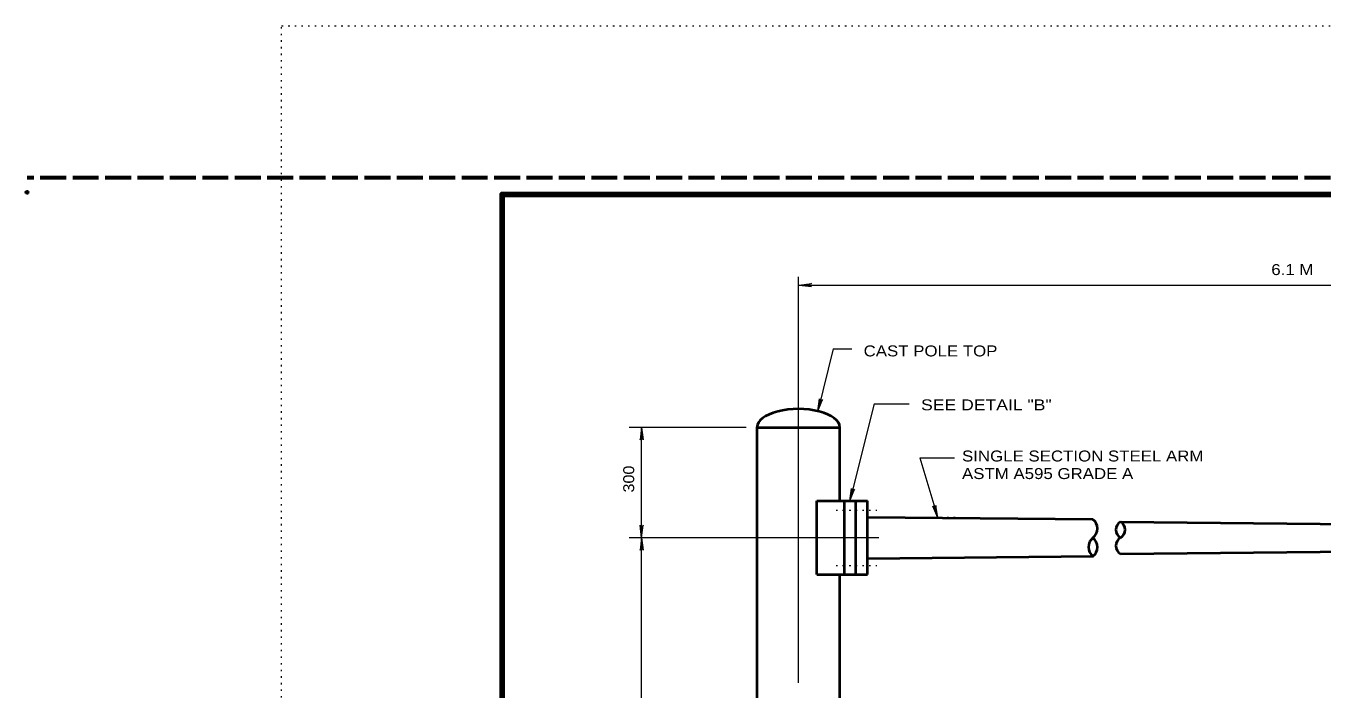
# Model space of a CAD drawing. Extents: x 312583 to 312854, y 144419 to 144597.
# Drawn here: x 312583.5 to 312673.4, y 144550.7 to 144596.8 of the extents above; entities that cross this region are included whole.
import ezdxf

# ---------------------------------------------------------------- set-up
doc = ezdxf.new("R2010")
doc.units = 0
doc.header["$LTSCALE"] = 0.3
doc.header["$PDMODE"] = 32
doc.header["$PDSIZE"] = 0.15
doc.linetypes.add('DOTTED', pattern=[1.5, 0.3, -1.2])
doc.linetypes.add('LONG_DASHED', pattern=[7.5, 6, -1.5])
for name, color, linetype, lineweight in [('1', 7, 'Continuous', 40), ('2', 7, 'Continuous', 13), ('62', 7, 'DOTTED', 13), ('63', 7, 'LONG_DASHED', 60)]:
    doc.layers.add(name, color=color, linetype=linetype, lineweight=lineweight)

msp = doc.modelspace()

# ---------------------------------------------------------------- linework, layer by layer
at = {"layer": '1'}
for p, q in [((312634.1997, 144568.9109), (312639.9497, 144568.9109)), ((312634.1997, 144531.5513), (312634.1997, 144568.9109)), ((312639.9497, 144563.7973), (312639.9497, 144568.9109)), ((312638.3473, 144563.7973), (312641.8663, 144563.7973)), ((312638.3473, 144558.6836), (312638.3473, 144563.7973)), ((312640.264, 144558.6836), (312640.264, 144563.7973)), ((312641.069, 144558.6836), (312641.069, 144563.7973)), ((312641.8663, 144558.6836), (312641.8663, 144563.7973)), ((312641.8663, 144562.6779), (312657.514, 144562.5246)), ((312659.4307, 144562.3559), (312685.9497, 144562.0876)), ((312641.8663, 144559.8029), (312657.5447, 144559.9639)), ((312659.4307, 144560.1249), (312685.9497, 144560.3933)), ((312638.3473, 144558.6836), (312641.8663, 144558.6836)), ((312639.9497, 144531.5513), (312639.9497, 144558.6836))]:
    msp.add_line(p, q, dxfattribs=at)
at = {"layer": '1', "linetype": 'DOTTED', "lineweight": 13}
for p, q in [((312639.6813, 144563.1609), (312642.518, 144563.1609)), ((312641.8663, 144562.6779), (312648.0533, 144562.6779)), ((312639.6813, 144559.3276), (312642.518, 144559.3276))]:
    msp.add_line(p, q, dxfattribs=at)
at = {"layer": '1', "lineweight": 158}
msp.add_lwpolyline([(312616.5, 144423.1446), (312616.5, 144585.0846), (312849, 144585.0846)], dxfattribs=at)
at = {"layer": '1'}
for centre, radius, start, end in [((312657.0179, 144561.8816), 0.8117, 307.90303, 52.09697), ((312659.7626, 144561.8001), 0.6489, 120.51024, 239.48976), ((312659.1038, 144561.8001), 0.6489, 300.51024, 59.48976), ((312658.0152, 144560.6006), 0.8117, 127.90303, 232.09697), ((312657.0179, 144560.6006), 0.8117, 307.90303, 52.09697), ((312659.7626, 144560.682), 0.6489, 120.51024, 239.48976)]:
    msp.add_arc(centre, radius, start, end, dxfattribs=at)
msp.add_ellipse((312637.0721, 144568.9077), major_axis=(2.875, 0), ratio=0.444444, start_param=6.2831853, end_param=9.424778, dxfattribs=at)
msp.add_point((312583.526, 144585.2246), dxfattribs=at)
at = {"layer": '2'}
for p, q in [((312637.0747, 144551.1703), (312637.0747, 144579.3683)), ((312637.1207, 144578.7933), (312637.987, 144578.9006)), ((312637.987, 144578.9006), (312637.711, 144578.7933)), ((312637.1207, 144578.7933), (312706.0747, 144578.7933)), ((312637.1207, 144578.7933), (312637.987, 144578.6859)), ((312637.987, 144578.6859), (312637.711, 144578.7933)), ((312639.4897, 144574.3619), (312638.4317, 144570.0303)), ((312639.4897, 144574.3619), (312640.77, 144574.3619)), ((312638.4317, 144570.0303), (312638.5313, 144570.8966)), ((312638.4317, 144570.0303), (312638.746, 144570.8506)), ((312638.5313, 144570.8966), (312638.5773, 144570.6053)), ((312638.746, 144570.8506), (312638.5773, 144570.6053)), ((312642.3417, 144570.5363), (312640.6473, 144563.7973)), ((312642.3417, 144570.5363), (312644.7643, 144570.5363)), ((312633.456, 144568.9109), (312625.3217, 144568.9109)), ((312626.188, 144568.9109), (312626.0807, 144568.0446)), ((312626.188, 144561.2443), (312626.188, 144568.9109)), ((312626.188, 144568.9109), (312626.2953, 144568.0446)), ((312626.0807, 144568.0446), (312626.188, 144568.3206)), ((312626.2953, 144568.0446), (312626.188, 144568.3206)), ((312645.4927, 144566.7873), (312647.9153, 144566.7873)), ((312645.4927, 144566.7873), (312646.7577, 144562.6319)), ((312640.6473, 144563.7973), (312640.7547, 144564.6636)), ((312640.6473, 144563.7973), (312640.9617, 144564.6099)), ((312640.7547, 144564.6636), (312640.793, 144564.3723)), ((312640.9617, 144564.6099), (312640.793, 144564.3723)), ((312646.405, 144563.4293), (312646.589, 144563.1916)), ((312646.7577, 144562.6319), (312646.405, 144563.4293)), ((312646.612, 144563.4906), (312646.589, 144563.1916)), ((312646.7577, 144562.6319), (312646.612, 144563.4906)), ((312626.0807, 144562.1106), (312626.188, 144561.8346)), ((312626.188, 144561.2443), (312626.0807, 144562.1106)), ((312626.2953, 144562.1106), (312626.188, 144561.8346)), ((312626.188, 144561.2443), (312626.2953, 144562.1106)), ((312642.6637, 144561.2443), (312625.3217, 144561.2443)), ((312626.188, 144561.2443), (312626.0807, 144560.3779)), ((312626.188, 144561.2443), (312626.2953, 144560.3779)), ((312626.188, 144494.3143), (312626.188, 144561.2443)), ((312626.0807, 144560.3779), (312626.188, 144560.6539)), ((312626.2953, 144560.3779), (312626.188, 144560.6539))]:
    msp.add_line(p, q, dxfattribs=at)
at = {"layer": '62'}
for p, q in [((312601.2, 144596.7846), (312853.5, 144596.7846)), ((312601.2, 144418.5846), (312601.2, 144596.7846))]:
    msp.add_line(p, q, dxfattribs=at)
at = {"layer": '63'}
msp.add_line((312851.75, 144586.2246), (312583.526, 144586.2246), dxfattribs=at)

# ---------------------------------------------------------------- texts
at = {"layer": '2'}
for s, width, p in [('6.1 M', 1.15, (312669.8959, 144579.4862)), ('CAST POLE TOP', 1.15, (312641.5993, 144573.8377)), ('SEE DETAIL "B"', 1.2, (312645.5849, 144570.0925)), ('SINGLE SECTION STEEL ARM', 1.15, (312648.429, 144566.5409)), ('ASTM A595 GRADE A', 1.15, (312648.429, 144565.3209))]:
    msp.add_text(s, height=0.76, dxfattribs=dict(at, width=width)).set_placement(p)
at = {"layer": '2', "width": 1.1}
msp.add_text('300', height=0.76, rotation=90, dxfattribs=at).set_placement((312625.673, 144564.3867))

doc.saveas('drawing.dxf')
